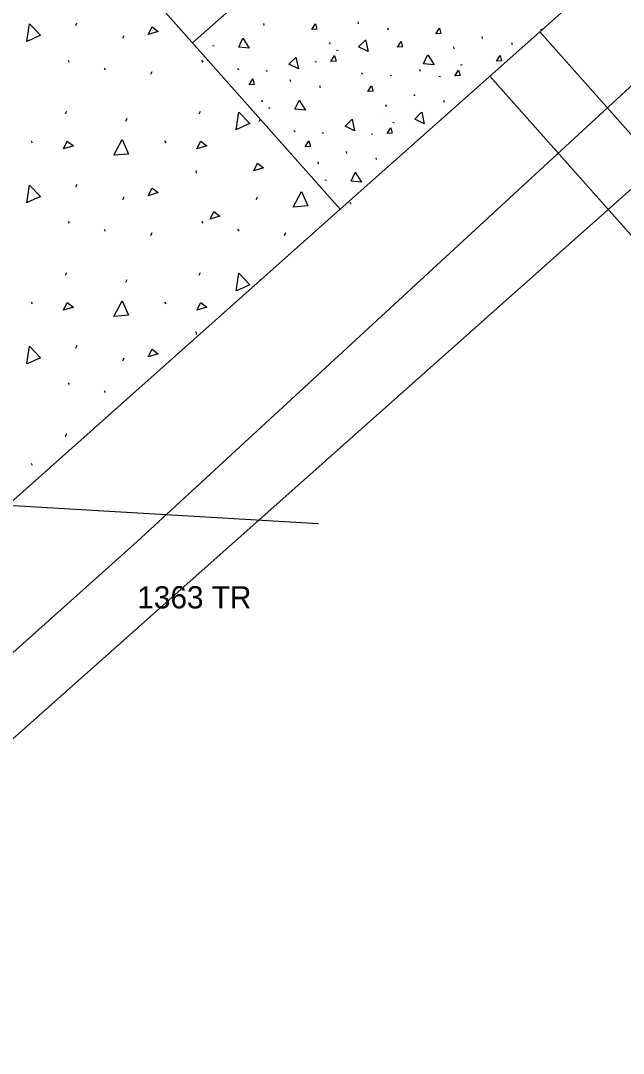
# Model space of a CAD drawing. Extents: x 50001 to 56005, y 49075 to 53926.
# Drawn here: x 53938.99 to 53966.09, y 51807.78 to 51854.17 of the extents above; entities that cross this region are included whole.
import ezdxf

# ---------------------------------------------------------------- set-up
doc = ezdxf.new("R2010")
doc.units = 0
for name, color, linetype in [('Level 11', 7, 'Continuous'), ('Level 12', 7, 'Continuous'), ('Level 15', 7, 'Continuous'), ('Level 20', 7, 'Continuous'), ('Level 61', 7, 'Continuous'), ('Level 8', 7, 'Continuous')]:
    doc.layers.add(name, color=color, linetype=linetype)

msp = doc.modelspace()

# ---------------------------------------------------------------- linework, layer by layer
at = {"layer": 'Level 11'}
for p, q in [((53944.235, 51830.768), (54450.301, 52297.6)), ((53245.856, 51207.553), (53944.235, 51830.768))]:
    msp.add_line(p, q, dxfattribs=at)
at = {"layer": 'Level 12'}
msp.add_line((53681.554, 51593.39), (53996.93, 51873.722), dxfattribs=at)
at = {"layer": 'Level 15'}
for p, q in [((53924.129, 51878.584), (53953.361, 51845.698)), ((53941.479, 51853.949), (53941.534, 51854.074)), ((53943.588, 51853.38), (53943.643, 51853.505)), ((53941.12, 51852.395), (53941.176, 51852.312)), ((53947.12, 51852.395), (53947.176, 51852.312)), ((53942.739, 51852.042), (53942.795, 51851.959)), ((53944.85, 51851.771), (53944.906, 51851.895)), ((53941.015, 51849.981), (53941.07, 51850.106)), ((53947.015, 51849.981), (53947.07, 51850.106)), ((53943.726, 51849.662), (53943.782, 51849.787)), ((53949.726, 51849.662), (53949.763, 51849.745)), ((53939.461, 51848.774), (53939.516, 51848.691)), ((53945.461, 51848.774), (53945.516, 51848.691)), ((53946.864, 51847.443), (53946.878, 51847.318)), ((53941.479, 51846.706), (53941.534, 51846.831)), ((53943.588, 51846.137), (53943.643, 51846.262)), ((53949.588, 51846.137), (53949.643, 51846.262)), ((53953.361, 51845.698), (53938.412, 51832.41)), ((53941.12, 51845.153), (53941.176, 51845.069)), ((53942.739, 51844.8), (53942.795, 51844.716)), ((53947.12, 51845.153), (53947.176, 51845.069)), ((53948.739, 51844.8), (53948.795, 51844.716)), ((53944.85, 51844.528), (53944.906, 51844.653)), ((53950.85, 51844.528), (53950.906, 51844.653)), ((53941.015, 51842.738), (53941.07, 51842.863)), ((53943.726, 51842.419), (53943.782, 51842.544)), ((53947.015, 51842.738), (53947.07, 51842.863)), ((53949.762, 51842.499), (53949.782, 51842.544)), ((53939.461, 51841.531), (53939.516, 51841.448)), ((53945.461, 51841.531), (53945.516, 51841.448)), ((53946.864, 51840.2), (53946.878, 51840.075)), ((53941.479, 51839.464), (53941.534, 51839.589)), ((53943.588, 51838.895), (53943.643, 51839.02)), ((53941.12, 51837.91), (53941.176, 51837.827)), ((53942.739, 51837.557), (53942.795, 51837.474)), ((53941.015, 51835.496), (53941.07, 51835.621)), ((53939.461, 51834.289), (53939.516, 51834.205)), ((53938.412, 51832.41), (53952.388, 51831.588))]:
    msp.add_line(p, q, dxfattribs=at)
for points in [[(53939.276, 51853.237), (53939.386, 51854.03), (53939.883, 51853.516), (53939.289, 51853.241)], [(53944.731, 51853.55), (53944.897, 51853.897), (53945.175, 51853.689), (53944.731, 51853.55)], [(53948.686, 51849.274), (53948.796, 51850.067), (53949.293, 51849.554), (53948.699, 51849.279)], [(53940.918, 51848.413), (53941.084, 51848.76), (53941.362, 51848.552), (53940.918, 51848.413)], [(53943.175, 51848.123), (53943.549, 51848.831), (53943.841, 51848.179), (53943.189, 51848.123)], [(53946.918, 51848.413), (53947.084, 51848.76), (53947.362, 51848.552), (53946.918, 51848.413)], [(53949.471, 51847.421), (53949.638, 51847.768), (53949.915, 51847.56), (53949.471, 51847.421)], [(53939.276, 51845.994), (53939.386, 51846.787), (53939.883, 51846.274), (53939.289, 51845.999)], [(53944.731, 51846.308), (53944.897, 51846.654), (53945.175, 51846.446), (53944.731, 51846.308)], [(53951.236, 51845.796), (53951.611, 51846.503), (53951.902, 51845.851), (53951.25, 51845.796)], [(53947.506, 51845.249), (53947.673, 51845.596), (53947.95, 51845.388), (53947.506, 51845.249)], [(53948.686, 51842.031), (53948.796, 51842.824), (53949.293, 51842.311), (53948.699, 51842.036)], [(53943.175, 51840.881), (53943.549, 51841.588), (53943.841, 51840.936), (53943.189, 51840.881)], [(53940.918, 51841.17), (53941.084, 51841.517), (53941.362, 51841.309), (53940.918, 51841.17)], [(53946.918, 51841.17), (53947.084, 51841.517), (53947.362, 51841.309), (53946.918, 51841.17)], [(53939.276, 51838.751), (53939.386, 51839.544), (53939.883, 51839.031), (53939.289, 51838.756)], [(53944.731, 51839.065), (53944.897, 51839.412), (53945.175, 51839.204), (53944.731, 51839.065)]]:
    msp.add_lwpolyline(points, dxfattribs=at)
at = {"layer": 'Level 20'}
msp.add_line((53946.717, 51853.172), (54189.74, 52069.191), dxfattribs=at)
at = {"layer": 'Level 8'}
for p, q in [((53953.361, 51845.698), (53964.572, 51855.663)), ((53954.145, 51854.116), (53954.17, 51854.029)), ((53949.904, 51854.042), (53949.93, 51853.955)), ((53955.48, 51853.843), (53955.506, 51853.755)), ((53962.329, 51853.67), (53983.508, 51829.844)), ((53962.374, 51853.809), (53962.4, 51853.722)), ((53952.818, 51853.136), (53952.818, 51853.136)), ((53952.87, 51853.198), (53952.895, 51853.11)), ((53959.72, 51853.463), (53959.746, 51853.376)), ((53961.056, 51853.189), (53961.082, 51853.102)), ((53947.684, 51853.02), (53947.62, 51853.039)), ((53952.691, 51853.028), (53952.691, 51853.028)), ((53953.26, 51852.82), (53953.196, 51852.839)), ((53958.446, 51852.998), (53958.471, 51852.91)), ((53952.284, 51852.302), (53952.22, 51852.32)), ((53958.267, 51852.375), (53958.267, 51852.375)), ((53958.394, 51852.483), (53958.394, 51852.483)), ((53948.802, 51851.966), (53948.741, 51852.024)), ((53950.089, 51851.894), (53950.025, 51851.913)), ((53954.378, 51851.766), (53954.317, 51851.824)), ((53956.929, 51851.991), (53956.955, 51851.903)), ((53958.836, 51852.167), (53958.772, 51852.185)), ((53951.094, 51851.53), (53951.119, 51851.442)), ((53955.665, 51851.694), (53955.601, 51851.713)), ((53957.86, 51851.648), (53957.796, 51851.667)), ((53960.087, 51851.677), (53981.278, 51827.837)), ((53952.43, 51851.256), (53952.455, 51851.168)), ((53956.67, 51850.876), (53956.695, 51850.789)), ((53949.819, 51850.611), (53949.845, 51850.523)), ((53955.395, 51850.411), (53955.421, 51850.323)), ((53958.006, 51850.602), (53958.031, 51850.515)), ((53950.209, 51850.233), (53950.145, 51850.252)), ((53955.344, 51849.896), (53955.344, 51849.896)), ((53955.216, 51849.788), (53955.216, 51849.788)), ((53955.785, 51849.58), (53955.721, 51849.598)), ((53951.327, 51849.18), (53951.266, 51849.237)), ((53952.614, 51849.107), (53952.55, 51849.126)), ((53954.809, 51849.061), (53954.745, 51849.08)), ((53953.619, 51848.289), (53953.644, 51848.202)), ((53952.344, 51847.824), (53952.37, 51847.736)), ((53954.955, 51848.015), (53954.98, 51847.928)), ((53952.734, 51846.993), (53952.67, 51847.011)), ((53953.852, 51845.939), (53953.791, 51845.996))]:
    msp.add_line(p, q, dxfattribs=at)
for points in [[(53952.243, 51854.037), (53952.308, 51853.788), (53952.077, 51853.775), (53952.243, 51854.037)], [(53957.819, 51853.837), (53957.884, 51853.589), (53957.653, 51853.575), (53957.819, 51853.837)], [(53948.984, 51853.388), (53949.27, 51852.937), (53948.796, 51852.984), (53948.98, 51853.38)], [(53954.495, 51853.306), (53954.609, 51852.784), (53954.18, 51852.99), (53954.488, 51853.3)], [(53956.093, 51853.24), (53956.158, 51852.992), (53955.927, 51852.978), (53956.093, 51853.24)], [(53951.365, 51852.528), (53951.479, 51852.006), (53951.05, 51852.212), (53951.358, 51852.522)], [(53953.105, 51852.604), (53953.17, 51852.356), (53952.939, 51852.343), (53953.105, 51852.604)], [(53957.291, 51852.637), (53957.577, 51852.186), (53957.103, 51852.233), (53957.287, 51852.629)], [(53960.548, 51852.61), (53960.613, 51852.362), (53960.382, 51852.348), (53960.548, 51852.61)], [(53958.681, 51851.951), (53958.746, 51851.703), (53958.515, 51851.689), (53958.681, 51851.951)], [(53949.426, 51851.555), (53949.491, 51851.307), (53949.26, 51851.293), (53949.426, 51851.555)], [(53954.768, 51851.25), (53954.833, 51851.002), (53954.602, 51850.988), (53954.768, 51851.25)], [(53951.509, 51850.601), (53951.795, 51850.15), (53951.321, 51850.197), (53951.505, 51850.593)], [(53957.02, 51850.065), (53957.134, 51849.544), (53956.705, 51849.75), (53957.013, 51850.059)], [(53953.89, 51849.741), (53954.005, 51849.22), (53953.575, 51849.426), (53953.883, 51849.735)], [(53955.63, 51849.364), (53955.695, 51849.116), (53955.464, 51849.102), (53955.63, 51849.364)], [(53951.951, 51848.768), (53952.016, 51848.52), (53951.785, 51848.506), (53951.951, 51848.768)], [(53954.034, 51847.36), (53954.32, 51846.91), (53953.847, 51846.956), (53954.03, 51847.352)]]:
    msp.add_lwpolyline(points, dxfattribs=at)

# ---------------------------------------------------------------- texts
at = {"layer": 'Level 61'}
msp.add_text('1363 TR', height=1, dxfattribs=at).set_placement((53944.235, 51827.768))

doc.saveas('drawing.dxf')
